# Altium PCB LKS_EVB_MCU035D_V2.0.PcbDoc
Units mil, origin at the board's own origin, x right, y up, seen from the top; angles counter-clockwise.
Board outline 1880 x 1275 mil, 2 copper layers (Top Layer, Bottom Layer); 21 components, 29 nets, 81 pads, 23 vias.
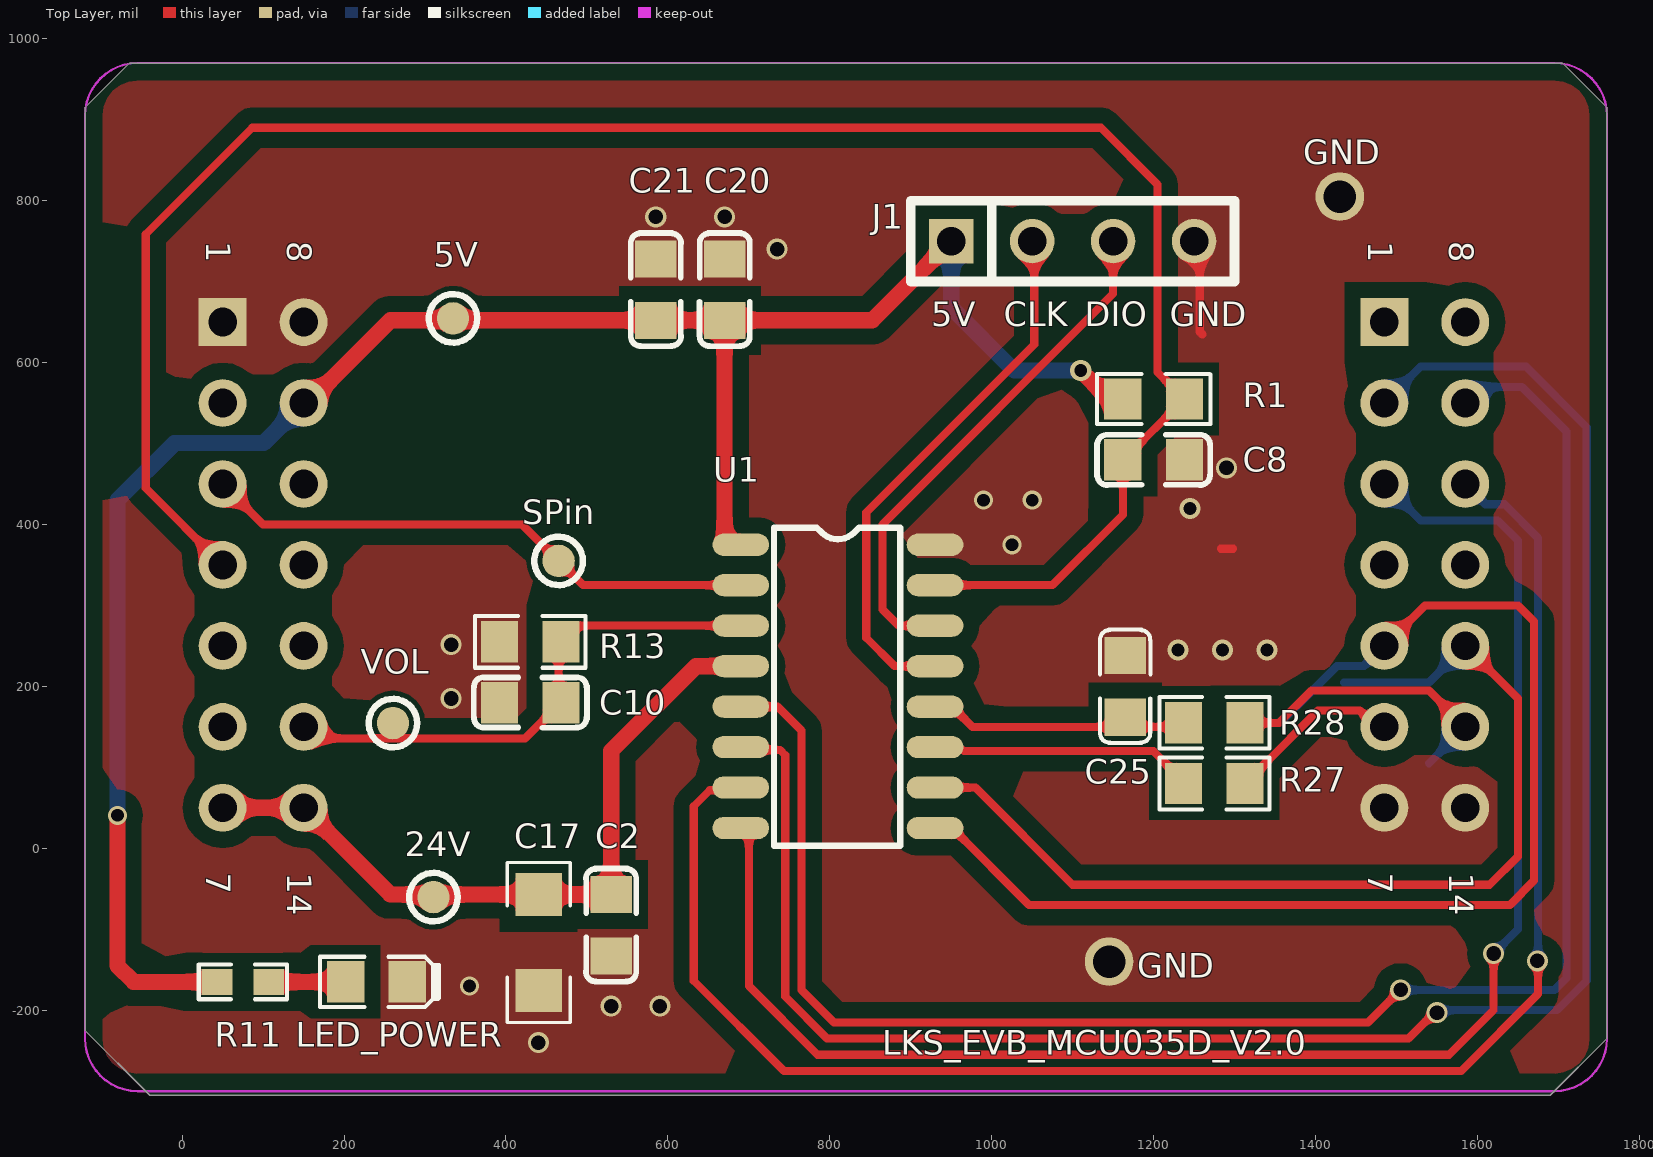
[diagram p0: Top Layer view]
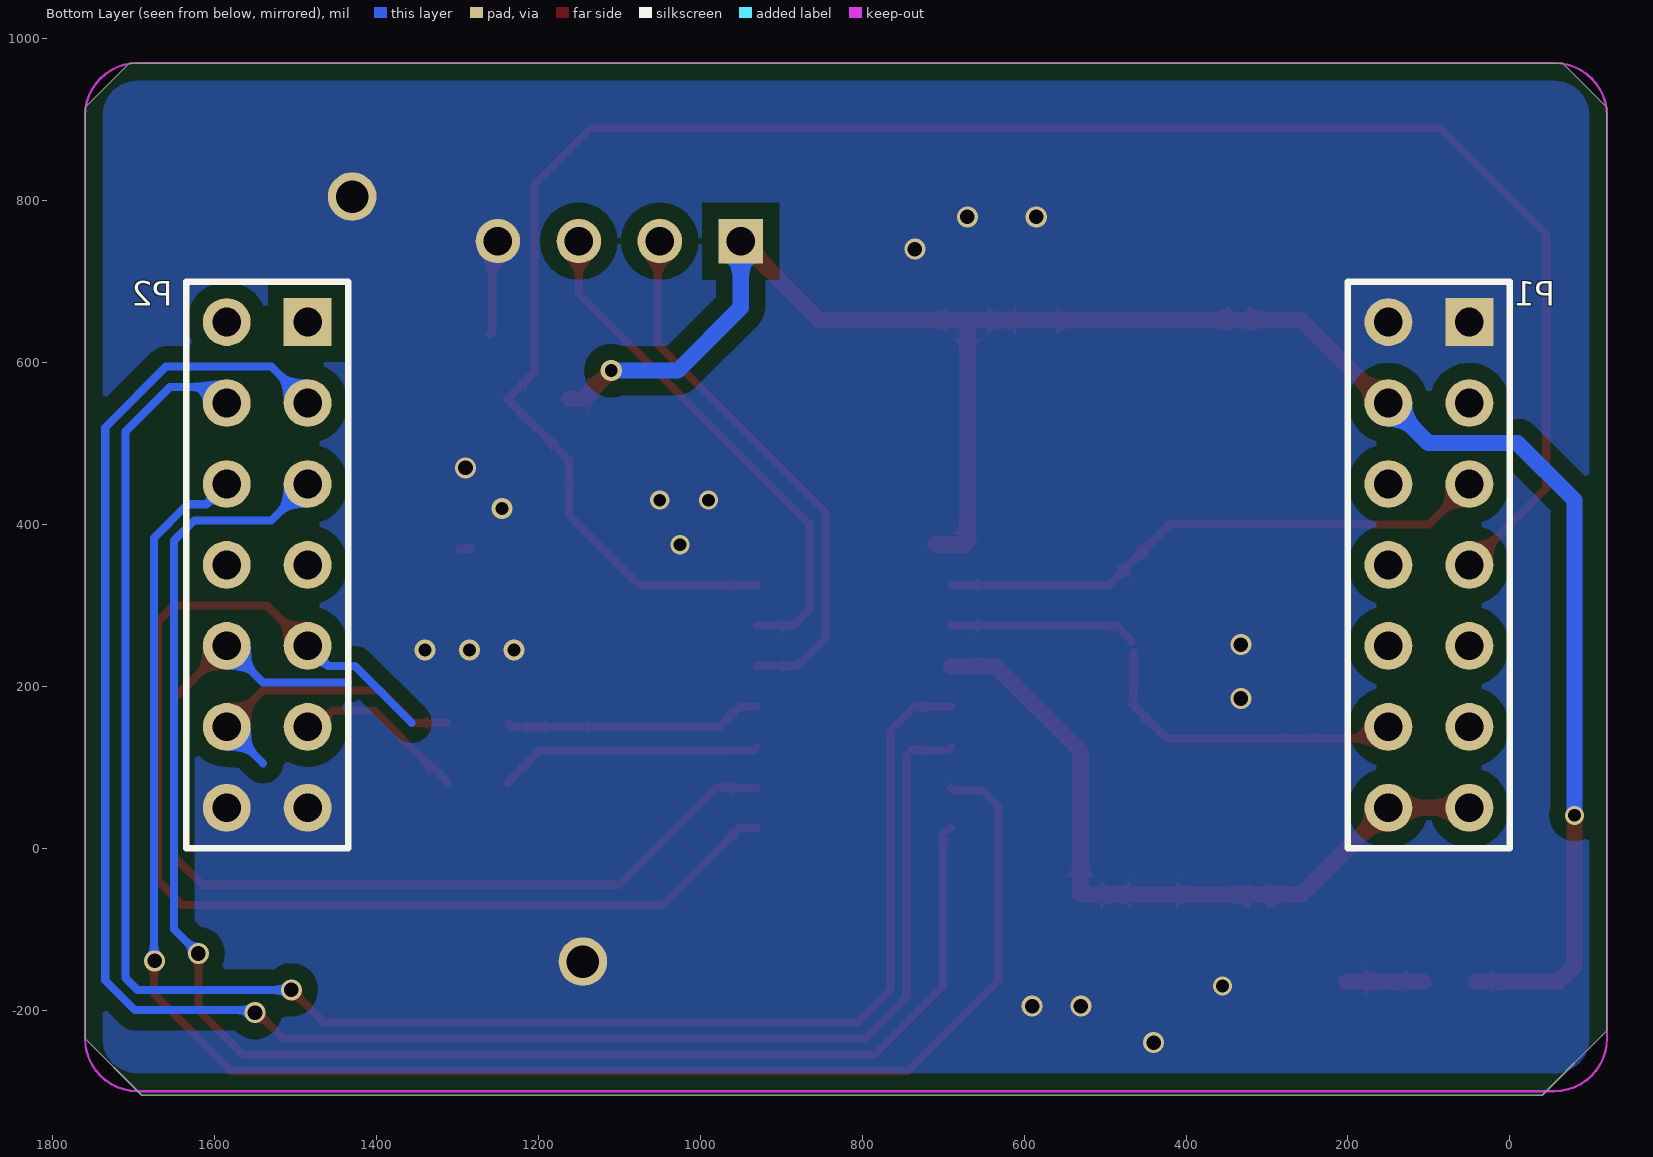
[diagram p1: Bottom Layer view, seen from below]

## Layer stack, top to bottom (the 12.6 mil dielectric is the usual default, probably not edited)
Top Solder: solder mask 0.4, Solder Resist, Dk 3.5
Top Layer: signal copper 1.4
Dielectric1: dielectric 12.6, FR-4, Dk 4.8
Bottom Layer: signal copper 1.4
Bottom Solder: solder mask 0.4, Solder Resist, Dk 3.5

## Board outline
-120,-225 -40,-305 1690,-305 1760,-235 1760,915 1705,970 -65,970 -120,915

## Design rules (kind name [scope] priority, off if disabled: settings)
Clearance Clearance_1 [INPolygon] p1: gap=20 ignorepadtopadclearanceinfootprint=FALSE except(0: Arc-Hole Track-Hole SMDPad-Hole THPad-Hole Via-Hole Fill-Hole Poly-Hole Region-Hole Text-Hole)
Clearance [All] p2: gap=10 ignorepadtopadclearanceinfootprint=FALSE except(0: Arc-Hole Track-Hole SMDPad-Hole THPad-Hole Via-Hole Fill-Hole Poly-Hole Region-Hole Text-Hole)
ComponentClearance [All] p1: gap=0 collisioncheckmode=3 verticalgap=0 showdistances=FALSE
FabricationTestpoint [(IsPad And (OnTopLayer Or OnBottomLayer))] p1: side=3 testpointundercomponent=TRUE minsize=40 maxsize=100 preferedsize=60 minholesize=0 maxholesize=40 preferedholesize=32 testpointgrid=1 allowsidetop=TRUE allowsidebottom=TRUE usegrid=TRUE gridtolerance=0.01
PolygonConnect [All] p1: connectstyle=Direct reliefconductorwidth=20 reliefentries=4 polygonreliefangle="90 Angle" airgapwidth=10
RoutingVias [All] p1: holewidth=28 width=50 viastyle="Through Hole" minholewidth=28 minwidth=50 maxholewidth=28 maxwidth=50
SilkToSolderMaskClearance SilkscreenOverComponentPads [IsPad] p1: minsilkscreentomaskgap=10 clearancetoexposedcopper=TRUE
SolderMaskExpansion [All] p1: expansion=4 istentingtop=FALSE
Width [All] p1: maxlimit=300 minlimit=1 preferedwidth=10
27 further rules are at their usual default settings.

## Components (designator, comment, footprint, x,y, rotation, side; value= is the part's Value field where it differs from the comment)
5V "TestP" TP-40 335,655 r0 top
24V "TestP" TP-40 310,-60 r90 top
C2 "100nF" 0805C 530,-95 r270 top
C8 "100nF" 0805C 1200,480 r0 top
C10 "100nF" 0805C 430,180 r180 top
C17 "10uF/50V" 1206 440,-175 r90 top
C20 "100nF" 0805C 670,690 r90 top
C21 "10uF/10V" 0805C 585,690 r90 top
C25 "100pF/50V" 0805C 1165,200 r270 top
J1 "SWD" SIP4-2.5 1100,750 r0 top
LED_POWER "" 0805D 240,-165 r0 top
P1 "Header 7X2A" HDR2X7_CEN 50,650 r270 bottom
P2 "Header 7X2A" HDR2X7_CEN 1485,650 r270 bottom
R1 "20K" 0805R 1200,555 r0 top
R11 "3.3K" 0603R 75,-165 r180 top
R13 "3.3K" 0805R 430,255 r180 top
R27 "1K" 0805R 1275,80 r0 top
R28 "1K" 0805R 1275,155 r0 top
SPin "TestP" TP-40 464.61,355.39 r90 top
U1 "LKS035D" SOP-16 690,375 r0 top
VOL "TestP" TP-40 260,155 r90 top

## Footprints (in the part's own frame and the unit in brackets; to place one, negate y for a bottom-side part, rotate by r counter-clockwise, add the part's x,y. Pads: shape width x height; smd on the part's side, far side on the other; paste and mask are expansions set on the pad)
0603R [mil]
  rect 38x32 smd: 1(-32,0) 2(32,0)
  silkscreen extent -54,-22 54,22, body extent -31,-16 32,16, height 18
0805C [mil]
  rect 46x51.18 smd: 1(-38,0) 2(38,0)
  silkscreen extent -70,-31 70,31
0805D [mil]
  rect 46x51.18 smd: 1(-38,0) 2(38,0)
  silkscreen extent -70,-31 77,31, body extent -39,-25 39,25, height 22
0805R [mil]
  rect 46x51.18 smd: 1(-38,0) 2(38,0)
  silkscreen extent -70,-31 70,31, body extent -39,-25 39,25, height 22
1206 [mm]
  rect 1.35x1.45 smd: 1(-0.01,-0.01) 2(2.99,-0.01)
  silkscreen extent -1.02,-1 4,0.98
HDR2X7_CEN [mm] "Connector; Header; 7x2 Position"
  rect 1.5x1.5 hole 0.9: 1(0,0)
  round 1.5 hole 0.9: 2(2.54,0) 3(5.08,0) 4(7.62,0) 5(10.16,0) 6(12.7,0) 7(15.24,0) 8(0,-2.54) 9(2.54,-2.54) 10(5.08,-2.54) 11(7.62,-2.54) 12(10.16,-2.54) 13(12.7,-2.54) 14(15.24,-2.54)
  silkscreen extent -1.27,-3.81 16.51,1.27
SIP4-2.5 [mil]
  rect 55x55 hole 35: 1(-150,0)
  round 55 hole 35: 2(-50,0) 3(50,0) 4(150,0)
  silkscreen extent -200,-50 200,50
SOP-16 [mil]
  round 15.75 on Top Overlay: 0(2,45)
  oval 70x27.56 smd: 1(0,0) 2(0,-50) 3(0,-100) 4(0,-150) 5(0,-200) 6(0,-250) 7(0,-300) 8(0,-350) 9(240,-350) 10(240,-300) 11(240,-250) 12(240,-200) 13(240,-150) 14(240,-100) 15(240,-50) 16(240,0)
  silkscreen extent 41,-372 197,21
TP-40 [mil] "测?"
  round 40 smd: 1(-0.39,-0.39)
  silkscreen extent -30,-30 30,30

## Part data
C2 C10 C17: library part CAP, "Capacitor"
C8 C20 C21 C25: library part C, "Capacitor"
J1: library part "Header 4", "Header, 4-Pin"
LED_POWER: library part LED2, "Typical RED, GREEN, YELLOW, AMBER GaAs LED"
P1 P2: "Header, 7-Pin, Dual row"
R1 R27 R28: library part RES2-1
R11 R13: library part Res2, "Resistor"
U1: library part LKS32MC035DL6S8, "CHIP"

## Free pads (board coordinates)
  round 60 hole 40: 6(1145,-140) 7(1430,805)

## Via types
v1: diameter 25.98, hole 17.99, Top Layer to Bottom Layer, 13 vias
v2: diameter 23.62, hole 15.75, Top Layer to Bottom Layer, 5 vias
v3: diameter 26, hole 16, Top Layer to Bottom Layer, 5 vias

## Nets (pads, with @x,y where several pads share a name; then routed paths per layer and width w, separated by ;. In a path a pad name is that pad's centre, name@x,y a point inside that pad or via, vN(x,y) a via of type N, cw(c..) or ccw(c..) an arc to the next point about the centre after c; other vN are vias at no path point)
5V: 5V.1 C20.1 C21.1 J1.1 P1.9 R1.1 R11.2 U1.1 | length 2518.8
  Top Layer w20: v2(-80,40.73) -80,-145 -60,-165 R11.2 ; P1.9@155,550 257.32,652.32 852.32,652.32 J1.1 ; C20.1 670,378.49 673.49,375 U1.1 U1.1@709.17,375 ; v3(1110,590) 1145,555 R1.1
  Bottom Layer w20: v2(-80,40.73) -80,430 -9.53,500.47 100.47,500.47 P1.9 ; J1.1 950,668 1028,590 v3(1110,590)
24V_MCU: 24V.1 C2.1 C17.2 P1.7 P1.14 U1.4 | length 905
  Top Layer w20: P1.7 P1.14 257,-57 C2.1 530,120.29 634.71,225 U1.4
FG: P1.2
G0: P2.13 R28.2 | length 370.8
  Top Layer w10: R28.2 1355,155 1395,195 1540,195 P2.13
  Bottom Layer w10: 1540,105 P2.13
G1: P2.4
G2: P2.1
GND: C2.2 C8.2 C10.2 C17.1 C20.2 C21.2 C25.1 J1.4 LED_POWER.2 P1.1 P1.8 P2.7 P2.14 pad.6 pad.7 R13.2 U1.16 | length 134.4
  Top Layer w10: J1.4 1256.94,743.06 1256.94,638.06 1260,635 ; 1283,370 1298.28,370
  other v1: 440,-240 530,-195 590,-195 332.17,185 332.24,251.63 1290,470 735,740 585,780 670,780
  other v2: 355,-170 1025,375 990,430 1050,430
  other v3: 1230,245 1285,245 1340,245 1245,420
GND0: P2.6 R27.2 | length 219.1
  Top Layer w10: R27.2 1313,82.59 1331,100.59 1333.59,100.59 1403,170 1454.61,170 1474.61,150 P2.6
HU&PU: P1.10
HV&PV: P1.11
HW&PW: P1.12
NetLED_POWER_1: LED_POWER.1 R11.1 | length 95
  Top Layer w20: R11.1 LED_POWER.1
NRST: C8.1 P1.4 R1.2 U1.15 | length 2503
  Top Layer w10: P1.4 -45,445 -45,758.43 86.57,890 1135,890 1205,820 1205,588 R1.2 1163,480 C8.1 1162,412 1075,325 U1.15
OPA3_IN: R27.1 U1.11 | length 327.2
  Top Layer w10: U1.11 933.36,121.64 964.22,121.64 965.86,120 1199.59,120 1237,82.59 R27.1
OPA3_IP: C25.2 R28.1 U1.12 | length 319.4
  Top Layer w10: U1.12 951.22,175 976.22,150 1232,150 R28.1
RXD: P1.6
SPIN: P1.3 SPin.1 U1.2 | length 691.8
  Top Layer w10: P1.3 100,400 420,400 495,325 U1.2
SWCLK: J1.2 U1.13 | length 676.5
  Top Layer w10: U1.13 880,225 845,260 845,415 1052.5,622.5 1052.5,747.5 J1.2
SWDIO: J1.3 U1.14 | length 646.3
  Top Layer w10: U1.14 885,275 865,295 865,400 1150,685 J1.3
TXD: P1.5
UH: P2.9 U1.5 | length 2223
  Top Layer w10: U1.5 735.31,175 765,145.31 765,-175 805,-215 1465,-215 v1(1505,-175)
  Bottom Layer w10: v1(1505,-175) 1695,-175 1710,-160 1710,515 1655,570 1605,570 P2.9
UL: P2.2 U1.6 | length 2381.5
  Top Layer w10: U1.6 693.36,121.64 738.36,121.64 745,115 745,-183.28 796.72,-235 1515,-235 1547.01,-202.99 v1(1550,-202.99)
  Bottom Layer w10: P2.2 1530,595 1660,595 1735,520 1735,-163.28 1698.28,-200 1552.99,-200 v1(1550,-202.99)
UX: P2.8
VH: P2.10 U1.7 | length 2093.4
  Top Layer w10: U1.7 686.64,71.64 651.64,71.64 631.98,51.98 631.98,-163.69 743.28,-275 1580,-275 1675,-180 1675,-140 v1(1674.03,-139.03)
  Bottom Layer w10: P2.10 1610,425 1633.28,425 1675,383.28 1675,-138.06 v1(1674.03,-139.03)
VL: P2.3 U1.8 | length 1964.7
  Top Layer w10: U1.8 691.89,25 700,16.89 700,-170 785,-255 1565,-255 1620,-200 v1(1620,-130)
  Bottom Layer w10: P2.3 1530,405 1625,405 1650,380 1650,-100 v1(1620,-130)
VOL: C10.1 P1.13 R13.1 U1.3 VOL.1 | length 632.9
  Top Layer w10: P1.13@150,155 169.41,135.59 423.59,135.59 C10.1 ; C10.1@465,185 R13.1@465,242 ; R13.1 468,257 486,275 U1.3
VX: P2.11
WH: P2.12 U1.10 | length 1239.8
  Top Layer w10: U1.10 980,75 1100,-45 1615,-45 1650,-10 1650,185 P2.12
  Bottom Layer w10: 1435,205 1540,205 P2.12
WL: P2.5 U1.9 | length 1493.4
  Top Layer w10: U1.9 951.22,25 1046.22,-70 1640,-70 1670,-40 1670,280 1650,300 1535,300 P2.5
  Bottom Layer w10: 1356.72,155 1426.72,225 1460,225 P2.5
pads on no net: U1.0

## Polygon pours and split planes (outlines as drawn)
GND on Top Layer "Bottom Layer-No Net" (solid, remove dead copper, pour order 3): -125,970 -125,-300 1750,-300 1755,-295 1755,970
GND on Bottom Layer "Bottom Layer-No Net" (solid, remove dead copper, pour order 4): -120,970 -120,-300 1755,-300 1760,-295 1760,970

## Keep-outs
Keep-Out Layer:
  lines w2.99: -120,-235 ccw(c-55,-235) -55,-300 ; -120,905 cw(c-55,905) -55,970 ; 1695,-300 ccw(c1695,-235) 1760,-235 ; 1695,970 cw(c1695,905) 1760,905
  lines w3: -120,-235 -120,905 ; -55,-300 1695,-300 ; -55,970 1695,970 ; 1760,-235 1760,905

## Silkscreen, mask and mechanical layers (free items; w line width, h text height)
Top Overlay:
  text "GND" at 1385,845 h30
  text "5V" at 925,645 h30
  text "CLK" at 1015,645 h30
  text "DIO" at 1115,645 h30
  text "GND" at 1220,645 h30
  text "GND" at 1180,-160 h30
  text "LKS_EVB_MCU035D_V2.0" at 865,-255 h30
